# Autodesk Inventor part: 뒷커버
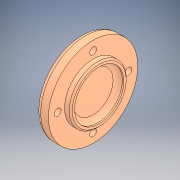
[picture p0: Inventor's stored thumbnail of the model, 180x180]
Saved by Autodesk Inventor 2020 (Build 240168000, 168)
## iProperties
Created: 2025-02
Part Number: 뒷커버
Material: 알루미늄 6061
Document SubType Name: Modeling
Designer: 1강의실14
Density: 2.7 g/cm^3
Appearance: 알루미늄 - 평지
Mass: 56.41 g
Surface Area: 76.8364 cm^2
Volume: 20.8926 cm^3
Sending System: Autodesk Inventor 2025
Preprocessor: ST-DEVELOPER v20
Author: jhkim
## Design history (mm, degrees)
feature "솔리드1"
node "솔리드2"
